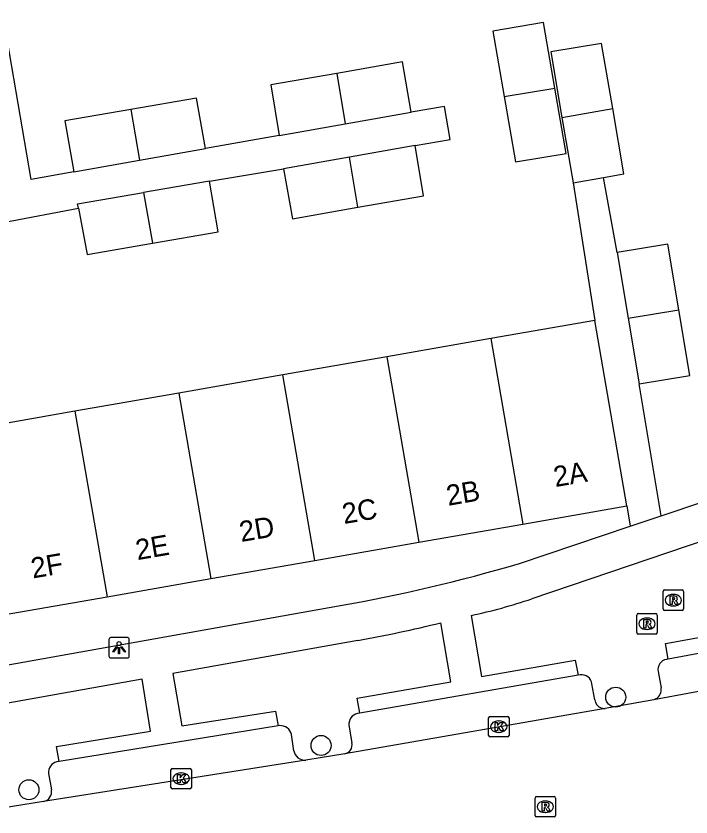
# Model space of a CAD drawing. Extents: x 160158 to 160921, y 381517 to 382041.
# Drawn here: x 160449.66 to 160482.63, y 381523.5 to 381562.61 of the extents above; entities that cross this region are included whole.
import ezdxf

# ---------------------------------------------------------------- set-up
doc = ezdxf.new("R2010")
doc.units = 0
for name, color, linetype in [('IMGEO_Boom', 7, 'Continuous'), ('IMGEO_Kolk', 7, 'Continuous'), ('IMGEO_Lichtpunt', 7, 'Continuous'), ('IMGEO_Pand', 7, 'Continuous'), ('IMGEO_Pand_nummerreeks', 7, 'Continuous'), ('IMGEO_Parkeervlak_open', 7, 'Continuous'), ('IMGEO_Rijbaan_lokaal_gesloten', 7, 'Continuous'), ('IMGEO_Rioolput', 7, 'Continuous'), ('IMGEO_Voetpad_open', 7, 'Continuous')]:
    doc.layers.add(name, color=color, linetype=linetype)

msp = doc.modelspace()

# ---------------------------------------------------------------- linework, layer by layer
at = {"layer": 'IMGEO_Boom'}
for centre in [(160478.955, 381529.354), (160464.563, 381526.996), (160450.295, 381524.834)]:
    msp.add_circle(centre, 0.489, dxfattribs=at)
at = {"layer": 'IMGEO_Kolk'}
for p, q in [((160472.744, 381527.489), (160472.744, 381528.341)), ((160472.819, 381528.415), (160473.671, 381528.415)), ((160473.232, 381528.195), (160473.257, 381528.195)), ((160473.745, 381528.341), (160473.745, 381527.489)), ((160473.671, 381527.415), (160472.819, 381527.415)), ((160473.255, 381527.635), (160473.23, 381527.635)), ((160457.307, 381525.875), (160458.159, 381525.875)), ((160457.232, 381524.949), (160457.232, 381525.801)), ((160457.72, 381525.655), (160457.745, 381525.655)), ((160458.233, 381525.801), (160458.233, 381524.949)), ((160457.743, 381525.095), (160457.718, 381525.095)), ((160458.159, 381524.875), (160457.307, 381524.875))]:
    msp.add_line(p, q, dxfattribs=at)
for points in [[(160472.744, 381527.489), (160472.744, 381528.341)], [(160472.819, 381528.415), (160473.671, 381528.415)], [(160473.745, 381528.341), (160473.745, 381527.489)], [(160473.065, 381528.115), (160473.188, 381528.115), (160473.188, 381527.964), (160473.318, 381528.115), (160473.482, 381528.115), (160473.336, 381527.964), (160473.489, 381527.715), (160473.337, 381527.715), (160473.252, 381527.879), (160473.188, 381527.812), (160473.188, 381527.715), (160473.065, 381527.715), (160473.065, 381528.115)], [(160473.671, 381527.415), (160472.819, 381527.415)], [(160457.307, 381525.875), (160458.159, 381525.875)], [(160457.232, 381524.949), (160457.232, 381525.801)], [(160457.553, 381525.575), (160457.676, 381525.575), (160457.676, 381525.424), (160457.806, 381525.575), (160457.97, 381525.575), (160457.824, 381525.424), (160457.977, 381525.175), (160457.825, 381525.175), (160457.74, 381525.339), (160457.676, 381525.272), (160457.676, 381525.175), (160457.553, 381525.175), (160457.553, 381525.575)], [(160458.233, 381525.801), (160458.233, 381524.949)], [(160458.159, 381524.875), (160457.307, 381524.875)]]:
    msp.add_lwpolyline(points, dxfattribs=at)
for centre, start, end in [((160472.821, 381528.339), 91.552, 178.448), ((160472.821, 381528.339), 91.552, 178.448), ((160473.669, 381528.339), 1.552, 88.448), ((160473.669, 381528.339), 1.552, 88.448), ((160472.821, 381527.491), 181.552, 268.448), ((160472.821, 381527.491), 181.552, 268.448), ((160473.669, 381527.491), 271.552, 358.448), ((160473.669, 381527.491), 271.552, 358.448), ((160457.309, 381525.799), 91.552, 178.448), ((160457.309, 381525.799), 91.552, 178.448), ((160458.157, 381525.799), 1.552, 88.448), ((160458.157, 381525.799), 1.552, 88.448), ((160457.309, 381524.951), 181.552, 268.448), ((160457.309, 381524.951), 181.552, 268.448), ((160458.157, 381524.951), 271.552, 358.448), ((160458.157, 381524.951), 271.552, 358.448)]:
    msp.add_arc(centre, 0.0765, start, end, dxfattribs=at)
for centre, major_axis, ratio, start_param, end_param in [((160473.231, 381527.915), (-0.387, 0.002), 0.722429, 4.712389, 7.853982), ((160473.256, 381527.915), (-0.39, 0.002), 0.717154, 1.570796, 4.712389), ((160457.719, 381525.375), (-0.387, 0.002), 0.722429, 4.712389, 7.853982), ((160457.744, 381525.375), (-0.39, 0.002), 0.717154, 1.570796, 4.712389)]:
    msp.add_ellipse(centre, major_axis=major_axis, ratio=ratio, start_param=start_param, end_param=end_param, dxfattribs=at)
at = {"layer": 'IMGEO_Lichtpunt'}
for p, q in [((160454.201, 381532.171), (160454.201, 381531.364)), ((160454.201, 381532.171), (160454.201, 381531.364)), ((160455.103, 381532.266), (160454.295, 381532.266)), ((160455.103, 381532.266), (160454.295, 381532.266)), ((160455.197, 381531.364), (160455.197, 381532.171)), ((160455.197, 381531.364), (160455.197, 381532.171)), ((160454.295, 381531.27), (160455.103, 381531.27)), ((160454.295, 381531.27), (160455.103, 381531.27))]:
    msp.add_line(p, q, dxfattribs=at)
for points in [[(160454.575, 381531.835), (160454.614, 381531.807), (160454.426, 381531.545), (160454.388, 381531.572), (160454.575, 381531.835)], [(160454.677, 381531.787), (160454.724, 381531.787), (160454.724, 381531.465), (160454.677, 381531.465), (160454.677, 381531.787)], [(160454.787, 381531.807), (160454.825, 381531.834), (160455.012, 381531.572), (160454.973, 381531.544), (160454.787, 381531.807)]]:
    msp.add_lwpolyline(points, dxfattribs=at)
msp.add_circle((160454.7, 381531.969), 0.0994, dxfattribs=at)
for centre, start, end in [((160454.295, 381532.171), 90, 180), ((160454.295, 381532.171), 90, 180), ((160455.103, 381532.171), 0, 90), ((160455.103, 381532.171), 0, 90), ((160454.295, 381531.364), 180, 270), ((160454.295, 381531.364), 180, 270), ((160455.103, 381531.364), 270, 0), ((160455.103, 381531.364), 270, 360)]:
    msp.add_arc(centre, 0.0946, start, end, dxfattribs=at)
at = {"layer": 'IMGEO_Pand'}
for points in [[(160475.975, 381559.091), (160475.423, 381562.29), (160472.955, 381561.865), (160473.505, 381558.678)], [(160478.807, 381558.093), (160478.267, 381561.274), (160475.779, 381560.855), (160476.33, 381557.662)], [(160468.967, 381557.915), (160468.547, 381560.371), (160465.328, 381559.809)], [(160465.328, 381559.809), (160462.108, 381559.246), (160462.522, 381556.771)], [(160465.328, 381559.809), (160465.745, 381557.343)], [(160473.505, 381558.678), (160475.975, 381559.091)], [(160473.505, 381558.678), (160474.055, 381555.491), (160476.527, 381555.892), (160475.975, 381559.091)], [(160458.917, 381556.139), (160458.48, 381558.601), (160455.265, 381558.046)], [(160455.265, 381558.046), (160452.049, 381557.491), (160452.482, 381555.001)], [(160455.265, 381558.046), (160455.7, 381555.57)], [(160465.745, 381557.343), (160468.967, 381557.915)], [(160476.33, 381557.662), (160478.807, 381558.093)], [(160478.363, 381554.735), (160479.347, 381554.912), (160478.807, 381558.093)], [(160476.33, 381557.662), (160476.88, 381554.468)], [(160462.522, 381556.771), (160465.745, 381557.343)], [(160455.7, 381555.57), (160458.917, 381556.139)], [(160469.158, 381556.283), (160465.946, 381555.721)], [(160466.365, 381553.275), (160469.568, 381553.836), (160469.158, 381556.283)], [(160452.482, 381555.001), (160455.7, 381555.57)], [(160465.946, 381555.721), (160462.733, 381555.158)], [(160466.365, 381553.275), (160465.946, 381555.721)], [(160462.733, 381555.158), (160463.161, 381552.714), (160466.365, 381553.275)], [(160459.109, 381554.545), (160455.889, 381553.993)], [(160456.337, 381551.521), (160459.534, 381552.069), (160459.109, 381554.545)], [(160476.88, 381554.468), (160478.363, 381554.735)], [(160452.709, 381553.232), (160452.669, 381553.44), (160455.889, 381553.993)], [(160455.889, 381553.993), (160456.337, 381551.521)], [(160452.709, 381553.232), (160453.139, 381550.972), (160456.337, 381551.521)], [(160482.038, 381548.27), (160481.496, 381551.473), (160479.024, 381551.065)], [(160479.024, 381551.065), (160479.563, 381547.861)], [(160479.563, 381547.861), (160482.038, 381548.27)], [(160480.101, 381544.656), (160482.58, 381545.066), (160482.038, 381548.27)], [(160477.931, 381547.747), (160472.851, 381546.86)], [(160479.49, 381538.693), (160477.931, 381547.747)], [(160479.563, 381547.861), (160480.101, 381544.656)], [(160472.851, 381546.86), (160467.771, 381545.973)], [(160472.851, 381546.86), (160474.414, 381537.806)], [(160467.771, 381545.973), (160462.69, 381545.085)], [(160467.771, 381545.973), (160469.338, 381536.918)], [(160462.69, 381545.085), (160457.61, 381544.198)], [(160464.261, 381536.031), (160462.69, 381545.085)], [(160457.61, 381544.198), (160452.53, 381543.311)], [(160457.61, 381544.198), (160459.185, 381535.143)], [(160452.53, 381543.311), (160447.476, 381542.428)], [(160452.53, 381543.311), (160454.109, 381534.256)], [(160474.414, 381537.806), (160479.49, 381538.693)], [(160469.338, 381536.918), (160474.414, 381537.806)], [(160464.261, 381536.031), (160469.338, 381536.918)], [(160459.185, 381535.143), (160464.261, 381536.031)], [(160454.109, 381534.256), (160459.185, 381535.143)], [(160449.033, 381533.368), (160454.109, 381534.256)]]:
    msp.add_lwpolyline(points, dxfattribs=at)
at = {"layer": 'IMGEO_Parkeervlak_open'}
for points in [[(160481.523, 381531.215), (160481.436, 381531.199)], [(160481.028, 381530.61), (160481.171, 381529.818)], [(160477.218, 381530.44), (160477.119, 381530.423)], [(160477.937, 381529.227), (160477.786, 381530.006)], [(160480.918, 381529.268), (160480.817, 381529.226)], [(160466.452, 381528.572), (160466.341, 381528.553)], [(160462.534, 381527.964), (160462.466, 381527.952)], [(160465.925, 381527.991), (160466.068, 381527.13)], [(160463.236, 381526.742), (160463.122, 381527.525)], [(160451.772, 381526.212), (160451.663, 381526.195)], [(160451.253, 381525.621), (160451.396, 381524.826)]]:
    msp.add_lwpolyline(points, dxfattribs=at)
for centre, radius, start, end in [((160481.505, 381530.715), 0.489, 98.1494, 192.4299), ((160477.299, 381529.958), 0.489, 5.651, 99.5833), ((160480.67, 381529.715), 0.511, 298.9878, 11.6074), ((160478.392, 381529.259), 0.456, 184.0233, 251.3488), ((160478.395, 381529.267), 0.465, 251.2844, 276.0352), ((160466.509, 381528.024), 0.584, 146.8865, 183.2102), ((160466.426, 381528.07), 0.49, 100.0318, 146.1909), ((160462.57, 381527.398), 0.567, 12.9135, 93.5966), ((160465.537, 381527.038), 0.539, 329.6496, 9.7961), ((160463.778, 381526.829), 0.548, 189.1485, 273.9191), ((160465.616, 381527.08), 0.497, 283.0255, 320.9101), ((160451.773, 381525.683), 0.523, 102.0895, 186.8351), ((160450.919, 381524.735), 0.486, 281.4389, 10.7623)]:
    msp.add_arc(centre, radius, start, end, dxfattribs=at)
at = {"layer": 'IMGEO_Rijbaan_lokaal_gesloten'}
for points in [[(160493.5, 381531.587), (160480.817, 381529.226)], [(160480.817, 381529.226), (160478.444, 381528.805)], [(160478.444, 381528.805), (160465.728, 381526.595)], [(160463.815, 381526.282), (160451.015, 381524.259)], [(160465.728, 381526.595), (160463.815, 381526.282)], [(160451.015, 381524.259), (160448.992, 381523.939)]]:
    msp.add_lwpolyline(points, dxfattribs=at)
at = {"layer": 'IMGEO_Rioolput'}
for p, q in [((160481.268, 381533.664), (160481.268, 381534.516)), ((160481.343, 381534.59), (160482.195, 381534.59)), ((160482.269, 381534.516), (160482.269, 381533.664)), ((160481.756, 381534.37), (160481.781, 381534.37)), ((160481.779, 381533.81), (160481.754, 381533.81)), ((160479.983, 381532.511), (160479.983, 381533.363)), ((160480.058, 381533.437), (160480.91, 381533.437)), ((160480.984, 381533.363), (160480.984, 381532.511)), ((160482.195, 381533.59), (160481.343, 381533.59)), ((160480.471, 381533.217), (160480.496, 381533.217)), ((160480.494, 381532.657), (160480.469, 381532.657)), ((160480.91, 381532.437), (160480.058, 381532.437)), ((160475.016, 381523.579), (160475.016, 381524.431)), ((160475.091, 381524.505), (160475.943, 381524.505)), ((160475.504, 381524.285), (160475.529, 381524.285)), ((160476.017, 381524.431), (160476.017, 381523.579)), ((160475.943, 381523.505), (160475.091, 381523.505)), ((160475.527, 381523.725), (160475.502, 381523.725))]:
    msp.add_line(p, q, dxfattribs=at)
for points in [[(160481.268, 381533.664), (160481.268, 381534.516)], [(160481.343, 381534.59), (160482.195, 381534.59)], [(160482.269, 381534.516), (160482.269, 381533.664)], [(160481.857, 381534.288), (160481.605, 381534.29), (160481.605, 381533.89)], [(160481.783, 381534.209), (160481.729, 381534.209), (160481.729, 381534.128)], [(160481.729, 381534.128), (160481.781, 381534.128)], [(160481.605, 381533.89), (160481.729, 381533.89), (160481.729, 381534.052), (160481.74, 381534.052)], [(160481.787, 381534.023), (160481.858, 381533.89), (160481.998, 381533.89), (160481.933, 381534.016)], [(160479.983, 381532.511), (160479.983, 381533.363)], [(160480.058, 381533.437), (160480.91, 381533.437)], [(160480.984, 381533.363), (160480.984, 381532.511)], [(160482.195, 381533.59), (160481.343, 381533.59)], [(160480.572, 381533.135), (160480.32, 381533.137), (160480.32, 381532.737)], [(160480.32, 381532.737), (160480.444, 381532.737), (160480.444, 381532.899), (160480.455, 381532.899)], [(160480.498, 381533.056), (160480.444, 381533.056), (160480.444, 381532.975)], [(160480.444, 381532.975), (160480.496, 381532.975)], [(160480.502, 381532.87), (160480.573, 381532.737), (160480.713, 381532.737), (160480.648, 381532.863)], [(160480.91, 381532.437), (160480.058, 381532.437)], [(160475.016, 381523.579), (160475.016, 381524.431)], [(160475.091, 381524.505), (160475.943, 381524.505)], [(160476.017, 381524.431), (160476.017, 381523.579)], [(160475.605, 381524.203), (160475.353, 381524.205), (160475.353, 381523.805)], [(160475.353, 381523.805), (160475.477, 381523.805), (160475.477, 381523.967), (160475.488, 381523.967)], [(160475.531, 381524.124), (160475.477, 381524.124), (160475.477, 381524.043)], [(160475.477, 381524.043), (160475.529, 381524.043)], [(160475.535, 381523.938), (160475.606, 381523.805), (160475.746, 381523.805), (160475.681, 381523.931)], [(160475.943, 381523.505), (160475.091, 381523.505)]]:
    msp.add_lwpolyline(points, dxfattribs=at)
for centre, radius, start, end in [((160481.345, 381534.514), 0.0765, 91.552, 178.448), ((160481.345, 381534.514), 0.0765, 91.552, 178.448), ((160482.193, 381534.514), 0.0765, 1.552, 88.448), ((160482.193, 381534.514), 0.0765, 1.552, 88.448), ((160481.765, 381534.317), 0.19, 274.7715, 282.9687), ((160481.789, 381534.113), 0.0964, 77.0061, 93.1865), ((160481.803, 381534.17), 0.0378, 276.6634, 79.6772), ((160481.856, 381534.178), 0.109, 350.3612, 89.416), ((160481.854, 381534.178), 0.112, 277.5842, 350.9817), ((160481.838, 381533.963), 0.108, 29.5134, 73.7905), ((160481.739, 381533.999), 0.0533, 26.0293, 88.6989), ((160480.06, 381533.361), 0.0765, 91.552, 178.448), ((160480.06, 381533.361), 0.0765, 91.552, 178.448), ((160480.908, 381533.361), 0.0765, 1.552, 88.448), ((160480.908, 381533.361), 0.0765, 1.552, 88.448), ((160481.345, 381533.666), 0.0765, 181.552, 268.448), ((160481.345, 381533.666), 0.0765, 181.552, 268.448), ((160482.193, 381533.666), 0.0765, 271.552, 358.448), ((160482.193, 381533.666), 0.0765, 271.552, 358.448), ((160480.454, 381532.846), 0.0533, 26.0293, 88.6989), ((160480.48, 381533.164), 0.19, 274.7715, 282.9687), ((160480.504, 381532.96), 0.0964, 77.0061, 93.1865), ((160480.518, 381533.017), 0.0378, 276.6634, 79.6772), ((160480.571, 381533.025), 0.109, 350.3612, 89.416), ((160480.569, 381533.025), 0.112, 277.5842, 350.9817), ((160480.553, 381532.81), 0.108, 29.5134, 73.7905), ((160480.06, 381532.513), 0.0765, 181.552, 268.448), ((160480.06, 381532.513), 0.0765, 181.552, 268.448), ((160480.908, 381532.513), 0.0765, 271.552, 358.448), ((160480.908, 381532.513), 0.0765, 271.552, 358.448), ((160475.093, 381524.429), 0.0765, 91.552, 178.448), ((160475.093, 381524.429), 0.0765, 91.552, 178.448), ((160475.941, 381524.429), 0.0765, 1.552, 88.448), ((160475.941, 381524.429), 0.0765, 1.552, 88.448), ((160475.487, 381523.914), 0.0533, 26.0293, 88.6989), ((160475.513, 381524.232), 0.19, 274.7715, 282.9687), ((160475.537, 381524.028), 0.0964, 77.0061, 93.1865), ((160475.551, 381524.085), 0.0378, 276.6634, 79.6772), ((160475.604, 381524.093), 0.109, 350.3612, 89.416), ((160475.602, 381524.093), 0.112, 277.5842, 350.9817), ((160475.586, 381523.878), 0.108, 29.5134, 73.7905), ((160475.093, 381523.581), 0.0765, 181.552, 268.448), ((160475.093, 381523.581), 0.0765, 181.552, 268.448), ((160475.941, 381523.581), 0.0765, 271.552, 358.448), ((160475.941, 381523.581), 0.0765, 271.552, 358.448)]:
    msp.add_arc(centre, radius, start, end, dxfattribs=at)
for centre, major_axis, ratio, start_param, end_param in [((160481.755, 381534.09), (-0.387, 0.002), 0.722429, 4.712389, 7.853982), ((160481.78, 381534.09), (-0.39, 0.002), 0.717154, 1.570796, 4.712389), ((160480.47, 381532.937), (-0.387, 0.002), 0.722429, 4.712389, 7.853982), ((160480.495, 381532.937), (-0.39, 0.002), 0.717154, 1.570796, 4.712389), ((160475.503, 381524.005), (-0.387, 0.002), 0.722429, 4.712389, 7.853982), ((160475.528, 381524.005), (-0.39, 0.002), 0.717154, 1.570796, 4.712389)]:
    msp.add_ellipse(centre, major_axis=major_axis, ratio=ratio, start_param=start_param, end_param=end_param, dxfattribs=at)
at = {"layer": 'IMGEO_Voetpad_open'}
for points in [[(160452.482, 381555.001), (160450.412, 381554.635), (160448.695, 381564.54)], [(160469.158, 381556.283), (160470.869, 381556.578), (160470.591, 381558.188), (160468.967, 381557.915)], [(160462.522, 381556.771), (160458.917, 381556.139)], [(160459.109, 381554.545), (160462.733, 381555.158)], [(160476.88, 381554.468), (160477.931, 381547.747)], [(160479.024, 381551.065), (160478.363, 381554.735)], [(160449.121, 381552.549), (160452.709, 381553.232)], [(160481.182, 381538.213), (160501.869, 381545.165), (160503.713, 381545.771)], [(160481.182, 381538.213), (160480.101, 381544.656)], [(160479.49, 381538.693), (160479.661, 381537.702)], [(160479.661, 381537.702), (160481.182, 381538.213)], [(160474.25, 381535.884), (160479.661, 381537.702)], [(160481.523, 381531.215), (160481.386, 381531.97), (160485.883, 381532.785), (160484.361, 381537.378), (160474.854, 381534.159)], [(160434.753, 381528.34), (160465.414, 381533.807)], [(160471.895, 381533.345), (160472.407, 381530.356), (160476.976, 381531.157), (160477.119, 381530.423)], [(160466.452, 381528.572), (160466.322, 381529.303), (160470.909, 381530.098), (160470.41, 381532.987)], [(160492.18, 381533.188), (160481.523, 381531.215)], [(160466.355, 381532.125), (160457.326, 381530.511), (160457.757, 381527.949), (160462.335, 381528.674), (160462.466, 381527.952)], [(160451.772, 381526.212), (160451.637, 381526.942), (160456.241, 381527.696), (160455.824, 381530.238), (160445.073, 381528.319), (160445.431, 381526.009), (160447.553, 381526.337), (160447.67, 381525.607)], [(160477.119, 381530.423), (160466.452, 381528.572)], [(160462.466, 381527.952), (160451.772, 381526.212)]]:
    msp.add_lwpolyline(points, dxfattribs=at)
for centre, radius, start, end in [((160451.739, 381611.815), 79.197, 279.94273, 286.51301), ((160466.938, 381557.151), 24.316, 281.7632, 288.9992), ((160455.627, 381592.561), 61.381, 280.06591, 283.93634)]:
    msp.add_arc(centre, radius, start, end, dxfattribs=at)

# ---------------------------------------------------------------- texts
at = {"layer": 'IMGEO_Pand_nummerreeks'}
for s, p in [('2A', (160476.006, 381539.61)), ('2B', (160470.773, 381538.695)), ('2C', (160465.684, 381537.805)), ('2D', (160460.663, 381536.928)), ('2E', (160455.595, 381536.042)), ('2F', (160450.485, 381535.148))]:
    msp.add_text(s, height=1, rotation=9.7174, dxfattribs=at).set_placement(p)

doc.saveas('drawing.dxf')
